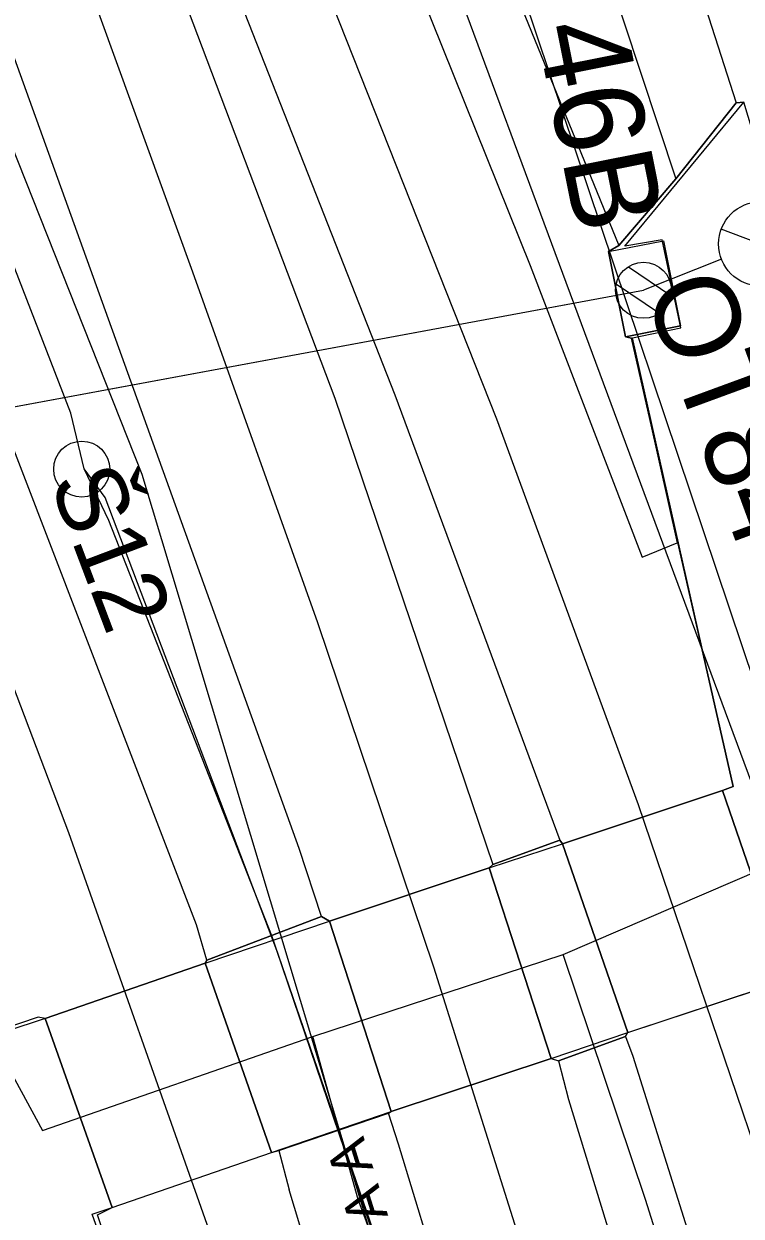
# Model space of a CAD drawing. Extents: x -545736 to -544888, y -1122892 to -1119128.
# Drawn here: x -545180.42 to -545167.61, y -1121712.96 to -1121691.68 of the extents above; entities that cross this region are included whole.
import ezdxf

# ---------------------------------------------------------------- set-up
doc = ezdxf.new("R2010")
doc.units = 0
for name, color, linetype in [('osvětlené plochy-hodnota-obrys', 7, 'Continuous'), ('Podbarveni_Komunikace', 7, 'Continuous'), ('Podbarveni_Prechodove konstrukce', 7, 'Continuous'), ('Vrstva 1 - Koleje', 7, 'Continuous'), ('Vrstva 11 - Trakce', 7, 'Continuous'), ('Vrstva 12 - Trakce zaklady', 7, 'Continuous'), ('Vrstva 16_plochy', 7, 'Continuous'), ('Vrstva 25', 7, 'Continuous'), ('Vrstva 28 - zabzar', 7, 'Continuous'), ('Vrstva 35', 7, 'Continuous'), ('Vrstva 4 - Teren - stezky - prechody - plochy', 7, 'Continuous'), ('Vrstva 43', 7, 'Continuous'), ('Vrstva 44', 7, 'Continuous'), ('Vrstva 6 - Navesti', 7, 'Continuous')]:
    doc.layers.add(name, color=color, linetype=linetype)

msp = doc.modelspace()

# ---------------------------------------------------------------- linework, layer by layer
at = {"layer": 'osvětlené plochy-hodnota-obrys'}
for points in [[(-545137.864, -1121889.42), (-545168.59, -1121731.992), (-545178.308, -1121699.721), (-545197.027, -1121652.528), (-545208.16, -1121619.35), (-545217.952, -1121591.114), (-545225.649, -1121565.547)], [(-545115.194, -1122188.84), (-545115.464, -1122158.52), (-545110.116, -1122078.531), (-545109.516, -1122044.98), (-545111.654, -1121993.485), (-545115.876, -1121955.778), (-545121.955, -1121920.051), (-545160.528, -1121723.806), (-545171.589, -1121690.909), (-545189.933, -1121650.816), (-545214.916, -1121599.46)]]:
    msp.add_lwpolyline(points, dxfattribs=at)
at = {"layer": 'Podbarveni_Komunikace'}
for p, q in [((-545169.574, -1121697.288), (-545167.756, -1121705.287)), ((-545167.756, -1121705.287), (-545167.946, -1121705.361)), ((-545167.946, -1121705.361), (-545166.787, -1121708.737)), ((-545170.805, -1121706.314), (-545170.851, -1121706.244)), ((-545169.634, -1121709.681), (-545170.805, -1121706.314)), ((-545172.114, -1121706.738), (-545171.005, -1121710.143)), ((-545174.966, -1121707.69), (-545175.107, -1121707.611)), ((-545173.862, -1121711.09), (-545174.966, -1121707.69)), ((-545177.184, -1121708.444), (-545175.997, -1121711.82)), ((-545178.847, -1121712.802), (-545180.039, -1121709.428)), ((-545175.871, -1121711.785), (-545173.909, -1121711.118)), ((-545173.909, -1121711.118), (-545173.862, -1121711.09)), ((-545175.997, -1121711.82), (-545175.871, -1121711.785))]:
    msp.add_line(p, q, dxfattribs=at)
for points in [[(-545167.565, -1121693.076), (-545167.703, -1121693.087), (-545168.781, -1121694.447), (-545169.795, -1121695.632), (-545169.981, -1121695.743)], [(-545169.981, -1121695.743), (-545169.679, -1121697.265), (-545169.574, -1121697.288)], [(-545170.851, -1121706.244), (-545172.048, -1121706.679), (-545172.114, -1121706.738)], [(-545175.107, -1121707.611), (-545177.153, -1121708.388), (-545177.184, -1121708.444)], [(-545180.039, -1121709.428), (-545180.163, -1121709.404), (-545182.89, -1121710.328), (-545181.985, -1121714.917)], [(-545171.005, -1121710.143), (-545170.872, -1121710.185), (-545169.68, -1121709.752), (-545169.634, -1121709.681)], [(-545178.637, -1121714.337), (-545179.104, -1121712.933), (-545178.847, -1121712.802)]]:
    msp.add_lwpolyline(points, dxfattribs=at)
at = {"layer": 'Podbarveni_Prechodove konstrukce'}
for p, q in [((-545167.946, -1121705.361), (-545170.805, -1121706.314)), ((-545166.787, -1121708.737), (-545167.946, -1121705.361)), ((-545170.805, -1121706.314), (-545169.634, -1121709.681)), ((-545172.114, -1121706.738), (-545174.966, -1121707.69)), ((-545171.005, -1121710.143), (-545172.114, -1121706.738)), ((-545174.966, -1121707.69), (-545173.862, -1121711.09)), ((-545177.184, -1121708.444), (-545180.039, -1121709.428)), ((-545175.997, -1121711.82), (-545177.184, -1121708.444)), ((-545169.634, -1121709.681), (-545166.787, -1121708.737)), ((-545180.039, -1121709.428), (-545178.847, -1121712.802)), ((-545173.862, -1121711.09), (-545171.005, -1121710.143)), ((-545178.847, -1121712.802), (-545175.997, -1121711.82))]:
    msp.add_line(p, q, dxfattribs=at)
at = {"layer": 'Vrstva 1 - Koleje'}
for points in [[(-545200.377, -1121638.127), (-545200.027, -1121638.835), (-545193.022, -1121653.026), (-545187.361, -1121668.627), (-545185.993, -1121672.41), (-545184.116, -1121677.602), (-545182.386, -1121682.379), (-545180.136, -1121688.593), (-545177.412, -1121696.104), (-545175.179, -1121702.365), (-545173.107, -1121708.51), (-545170.943, -1121715.381), (-545168.904, -1121722.322), (-545166.838, -1121730.016), (-545165.721, -1121734.52), (-545165.378, -1121735.902), (-545163.622, -1121743.653), (-545162.109, -1121751.114), (-545160.876, -1121757.439), (-545159.51, -1121764.477), (-545158.293, -1121770.72), (-545156.873, -1121778.046)], [(-545200.377, -1121638.127), (-545200.027, -1121638.835), (-545193.022, -1121653.026), (-545185.653, -1121667.954), (-545182.618, -1121674.124), (-545180.75, -1121678.05), (-545177.273, -1121685.741), (-545175.056, -1121690.975), (-545171.981, -1121698.73), (-545169.454, -1121705.612), (-545167.151, -1121712.394), (-545165.943, -1121716.253), (-545164.96, -1121719.394), (-545162.82, -1121726.889), (-545161.406, -1121732.291), (-545159.388, -1121740.831), (-545157.763, -1121748.706), (-545156.207, -1121756.669), (-545155.623, -1121759.664)], [(-545185.383, -1121691.101), (-545182.479, -1121698.59), (-545179.623, -1121706.109), (-545177.117, -1121713.199), (-545175.826, -1121717.114), (-545175.044, -1121719.485), (-545172.193, -1121729.1), (-545169.655, -1121738.82), (-545167.452, -1121748.582), (-545165.503, -1121758.451), (-545163.6, -1121768.21), (-545161.69, -1121777.988), (-545159.773, -1121787.837), (-545157.871, -1121797.594), (-545155.965, -1121807.383), (-545154.069, -1121817.086), (-545152.127, -1121827.047), (-545150.241, -1121836.711), (-545148.328, -1121846.526), (-545146.419, -1121856.308)]]:
    msp.add_lwpolyline(points, dxfattribs=at)
at = {"layer": 'Vrstva 11 - Trakce'}
for p, q in [((-545169.628, -1121696.017), (-545168.869, -1121696.525)), ((-545190.052, -1121700.262), (-545169.358, -1121696.433)), ((-545169.842, -1121696.324), (-545169.072, -1121696.839))]:
    msp.add_line(p, q, dxfattribs=at)
msp.add_circle((-545169.358, -1121696.433), 0.5, dxfattribs=at)
at = {"layer": 'Vrstva 12 - Trakce zaklady'}
for p, q in [((-545169.981, -1121695.743), (-545169, -1121695.548)), ((-545169.679, -1121697.265), (-545168.698, -1121697.07))]:
    msp.add_line(p, q, dxfattribs=at)
for points in [[(-545169.679, -1121697.265), (-545169.981, -1121695.743), (-545169, -1121695.548), (-545168.698, -1121697.07), (-545169.679, -1121697.265)], [(-545169.981, -1121695.743), (-545169.981, -1121695.743), (-545169.679, -1121697.265), (-545169.679, -1121697.265)]]:
    msp.add_lwpolyline(points, dxfattribs=at)
at = {"layer": 'Vrstva 16_plochy'}
for points in [[(-545167.946, -1121705.361), (-545167.756, -1121705.287), (-545169.555, -1121697.284), (-545168.69, -1121697.105), (-545169.025, -1121695.532), (-545169.693, -1121695.644), (-545167.565, -1121693.076)], [(-545167.946, -1121705.361), (-545166.787, -1121708.737), (-545164.43, -1121707.942), (-545164.961, -1121704.727), (-545165.743, -1121699.9), (-545166.266, -1121697.364), (-545167.565, -1121693.076)], [(-545172.114, -1121706.738), (-545170.805, -1121706.314), (-545169.634, -1121709.681)], [(-545172.114, -1121706.738), (-545171.005, -1121710.143), (-545169.634, -1121709.681)], [(-545175.997, -1121711.82), (-545177.184, -1121708.444), (-545174.966, -1121707.69), (-545173.862, -1121711.09)], [(-545181.959, -1121714.966), (-545178.683, -1121714.378), (-545179.201, -1121712.924), (-545178.847, -1121712.802), (-545180.039, -1121709.428), (-545182.857, -1121710.357), (-545181.959, -1121714.966)], [(-545175.997, -1121711.82), (-545173.862, -1121711.09)]]:
    msp.add_lwpolyline(points, dxfattribs=at)
at = {"layer": 'Vrstva 25'}
for p, q in [((-545166.561, -1121695.882), (-545167.968, -1121695.34)), ((-545167.964, -1121695.88), (-545169.358, -1121696.433))]:
    msp.add_line(p, q, dxfattribs=at)
msp.add_lwpolyline([(-545190.052, -1121700.262), (-545169.358, -1121696.433)], dxfattribs=at)
msp.add_circle((-545167.262, -1121695.605), 0.754, dxfattribs=at)
at = {"layer": 'Vrstva 28 - zabzar'}
for points in [[(-545182.64, -1121705.35), (-545181.62, -1121708.62), (-545180.09, -1121711.43)], [(-545180.09, -1121711.43), (-545175.26, -1121709.75), (-545170.79, -1121708.29), (-545166.27, -1121706.34), (-545164.44, -1121706.86), (-545163.18, -1121706.44), (-545161.12, -1121706.05), (-545159.98, -1121705.66)], [(-545163.02, -1121733.83), (-545163.14, -1121732.59), (-545163.95, -1121731.4), (-545167.62, -1121718.06), (-545169.32, -1121712.66), (-545170.79, -1121708.29)], [(-545173.13, -1121717.83), (-545172.48, -1121718.17), (-545173.11, -1121716.25), (-545174.45, -1121712.66), (-545175.26, -1121709.75)]]:
    msp.add_lwpolyline(points, dxfattribs=at)
at = {"layer": 'Vrstva 35'}
msp.add_lwpolyline([(-545180.09, -1121711.43), (-545175.26, -1121709.75), (-545170.79, -1121708.29), (-545166.27, -1121706.34)], dxfattribs=at)
at = {"layer": 'Vrstva 4 - Teren - stezky - prechody - plochy'}
for p, q in [((-545167.946, -1121705.361), (-545170.805, -1121706.314)), ((-545166.787, -1121708.737), (-545167.946, -1121705.361)), ((-545170.805, -1121706.314), (-545169.634, -1121709.681)), ((-545174.966, -1121707.69), (-545172.114, -1121706.738)), ((-545172.114, -1121706.738), (-545171.005, -1121710.143)), ((-545173.862, -1121711.09), (-545174.966, -1121707.69)), ((-545177.184, -1121708.444), (-545180.039, -1121709.428)), ((-545175.997, -1121711.82), (-545177.184, -1121708.444)), ((-545169.634, -1121709.681), (-545166.787, -1121708.737)), ((-545180.039, -1121709.428), (-545178.847, -1121712.802)), ((-545171.005, -1121710.143), (-545173.862, -1121711.09)), ((-545178.847, -1121712.802), (-545175.997, -1121711.82))]:
    msp.add_line(p, q, dxfattribs=at)
for points in [[(-545216.868, -1121596.848), (-545216.019, -1121596.395), (-545211.21, -1121604.274), (-545206.839, -1121610.949), (-545199.048, -1121622.889), (-545192.587, -1121633.352), (-545188.426, -1121640.975), (-545184.233, -1121649.302), (-545180.4, -1121658.058), (-545176.327, -1121668.124), (-545171.563, -1121681.077), (-545167.703, -1121693.087), (-545168.781, -1121694.447)], [(-545216.868, -1121596.848), (-545213.889, -1121604.829), (-545210.471, -1121613.16), (-545202.274, -1121630.693), (-545185.773, -1121664.159), (-545180.599, -1121674.576), (-545175.283, -1121686.286), (-545171.383, -1121695.992), (-545169.382, -1121701.199), (-545168.755, -1121700.94)], [(-545209.004, -1121612.298), (-545208.216, -1121611.839), (-545200.504, -1121623.754), (-545192.69, -1121636.392), (-545188.479, -1121644.031), (-545185.244, -1121650.818), (-545181.822, -1121658.643), (-545177.576, -1121669.097), (-545173.15, -1121681.254), (-545168.781, -1121694.447)], [(-545209.004, -1121612.298), (-545202.175, -1121627.489), (-545200.979, -1121629.68), (-545184.318, -1121663.578), (-545177.85, -1121676.702), (-545177.318, -1121678.004), (-545173.918, -1121685.556), (-545169.795, -1121695.632), (-545169.981, -1121695.743), (-545169.679, -1121697.265), (-545169.574, -1121697.288), (-545168.755, -1121700.94)], [(-545177.153, -1121708.388), (-545177.337, -1121707.756), (-545186.682, -1121683.465), (-545192.636, -1121667.775), (-545200.255, -1121645.889), (-545203.013, -1121638.235), (-545202.124, -1121637.845)], [(-545177.153, -1121708.388), (-545175.107, -1121707.611), (-545175.507, -1121706.398), (-545184.454, -1121681.584), (-545189.524, -1121667.292), (-545194.023, -1121655.906), (-545198.205, -1121646.356), (-545202.124, -1121637.845)], [(-545177.253, -1121689.509), (-545178.086, -1121689.845), (-545174.87, -1121698.36), (-545172.048, -1121706.679)], [(-545177.253, -1121689.509), (-545173.797, -1121698.297), (-545170.851, -1121706.244), (-545172.048, -1121706.679)], [(-545169.574, -1121697.288), (-545169.679, -1121697.265), (-545169.981, -1121695.743), (-545169.795, -1121695.632), (-545168.781, -1121694.447), (-545167.703, -1121693.087), (-545167.565, -1121693.076)], [(-545170.805, -1121706.314), (-545167.946, -1121705.361), (-545167.756, -1121705.287), (-545169.574, -1121697.288)], [(-545174.966, -1121707.69), (-545172.114, -1121706.738), (-545172.048, -1121706.679), (-545170.851, -1121706.244), (-545170.805, -1121706.314)], [(-545180.039, -1121709.428), (-545177.184, -1121708.444), (-545177.153, -1121708.388), (-545175.107, -1121707.611), (-545174.966, -1121707.69)], [(-545171.005, -1121710.143), (-545170.872, -1121710.185), (-545169.68, -1121709.752), (-545169.634, -1121709.681), (-545166.787, -1121708.737)], [(-545180.039, -1121709.428), (-545180.163, -1121709.404), (-545182.89, -1121710.328), (-545181.985, -1121714.917), (-545180.848, -1121720.815), (-545179.628, -1121726.7), (-545177.717, -1121736.49), (-545175.814, -1121746.279), (-545173.137, -1121759.988), (-545171.232, -1121769.763), (-545170.096, -1121775.61), (-545168.189, -1121785.44), (-545166.652, -1121793.283), (-545164.749, -1121803.058), (-545162.839, -1121812.848), (-545160.922, -1121822.667), (-545159.009, -1121832.498), (-545157.103, -1121842.273), (-545155.195, -1121852.046), (-545153.289, -1121861.829)], [(-545169.68, -1121709.752), (-545170.872, -1121710.185), (-545170.694, -1121710.876), (-545167.623, -1121720.902), (-545165.192, -1121730.272), (-545163.048, -1121739.109), (-545160.653, -1121750.397), (-545159.039, -1121758.75), (-545157.412, -1121758.312)], [(-545169.68, -1121709.752), (-545169.545, -1121710.101), (-545166.403, -1121720.085), (-545163.394, -1121730.631), (-545161.465, -1121738.363), (-545159.201, -1121749.439), (-545157.412, -1121758.312)], [(-545175.997, -1121711.82), (-545175.871, -1121711.785), (-545173.909, -1121711.118), (-545173.862, -1121711.09), (-545171.005, -1121710.143)], [(-545130.358, -1121950.008), (-545129.391, -1121949.959), (-545129.73, -1121942.596), (-545130.115, -1121934.948), (-545130.824, -1121927.405), (-545131.836, -1121918.196), (-545133.344, -1121907.479), (-545134.953, -1121898.499), (-545142.937, -1121857.697), (-545151.741, -1121812.566), (-545162.39, -1121757.819), (-545164.226, -1121748.401), (-545166.939, -1121735.985), (-545169.746, -1121724.99), (-545172.237, -1121716.559), (-545173.733, -1121711.673), (-545173.909, -1121711.118), (-545175.871, -1121711.785), (-545175.683, -1121712.485)], [(-545176.589, -1121720.029), (-545178.637, -1121714.337), (-545179.104, -1121712.933), (-545178.847, -1121712.802), (-545175.997, -1121711.82)], [(-545130.358, -1121950.008), (-545130.752, -1121943), (-545131.52, -1121935.35), (-545132.155, -1121927.829), (-545133.341, -1121918.921), (-545135.127, -1121907.455), (-545136.587, -1121899.196), (-545144.41, -1121858.134), (-545153.364, -1121812.756), (-545162.564, -1121765.529), (-545165.788, -1121749.365), (-545168.396, -1121737.4), (-545171.828, -1121724.869), (-545174.108, -1121717.697), (-545175.683, -1121712.485)]]:
    msp.add_lwpolyline(points, dxfattribs=at)
at = {"layer": 'Vrstva 43'}
msp.add_circle((-545179.388, -1121699.625), 0.5, dxfattribs=at)
at = {"layer": 'Vrstva 44'}
for points in [[(-545154.066, -1121755.488), (-545156.631, -1121743.461), (-545160.096, -1121730.567), (-545160.85, -1121728.368), (-545161.141, -1121726.228), (-545163.34, -1121716.222), (-545164.049, -1121714.326), (-545174.37, -1121686.504), (-545186.53, -1121660.015), (-545186.844, -1121659.528)], [(-545139.779, -1121877.836), (-545147.175, -1121839.811), (-545147.369, -1121839.002), (-545147.437, -1121838.152), (-545155.452, -1121797.558), (-545155.595, -1121796.474), (-545155.658, -1121796.154), (-545157.036, -1121788.893), (-545157.839, -1121784.658), (-545161.523, -1121765.245), (-545161.723, -1121764.693), (-545161.769, -1121763.91), (-545164.033, -1121753.897), (-545169.852, -1121728.16), (-545170.129, -1121727.27), (-545170.396, -1121726.56), (-545170.338, -1121725.182), (-545172.293, -1121718.704), (-545175.993, -1121707.957), (-545178.907, -1121700.544), (-545179.343, -1121699.618), (-545179.583, -1121698.628), (-545193.322, -1121663.167)], [(-545139.513, -1121878.622), (-545139.749, -1121877.759), (-545147.249, -1121839.292), (-545147.369, -1121839.002), (-545147.48, -1121838.112), (-545155.446, -1121797.363), (-545155.595, -1121796.474), (-545155.706, -1121795.975), (-545161.592, -1121765.233), (-545161.723, -1121764.693), (-545161.847, -1121763.916), (-545167.672, -1121738.027), (-545170.022, -1121727.953), (-545170.129, -1121727.27), (-545170.34, -1121725.169), (-545172.277, -1121718.871), (-545175.906, -1121708.217), (-545178.967, -1121700.134), (-545179.343, -1121699.618)]]:
    msp.add_lwpolyline(points, dxfattribs=at)

# ---------------------------------------------------------------- texts
at = {"layer": 'Vrstva 11 - Trakce'}
msp.add_text('46B', height=1.6, rotation=281.223, dxfattribs=at).set_placement((-545171.28, -1121691.75))
at = {"layer": 'Vrstva 25'}
msp.add_text('OT84', height=1.5, rotation=290.1627, dxfattribs=at).set_placement((-545169.358, -1121696.433))
at = {"layer": 'Vrstva 43'}
msp.add_text('Š12', height=1.25, rotation=290.7415, dxfattribs=at).set_placement((-545179.972, -1121699.846))
at = {"layer": 'Vrstva 6 - Navesti'}
msp.add_text('  F A A A A A A ', height=0.7, rotation=107.2839, dxfattribs=at).set_placement((-545172.462, -1121717.622))

doc.saveas('drawing.dxf')
